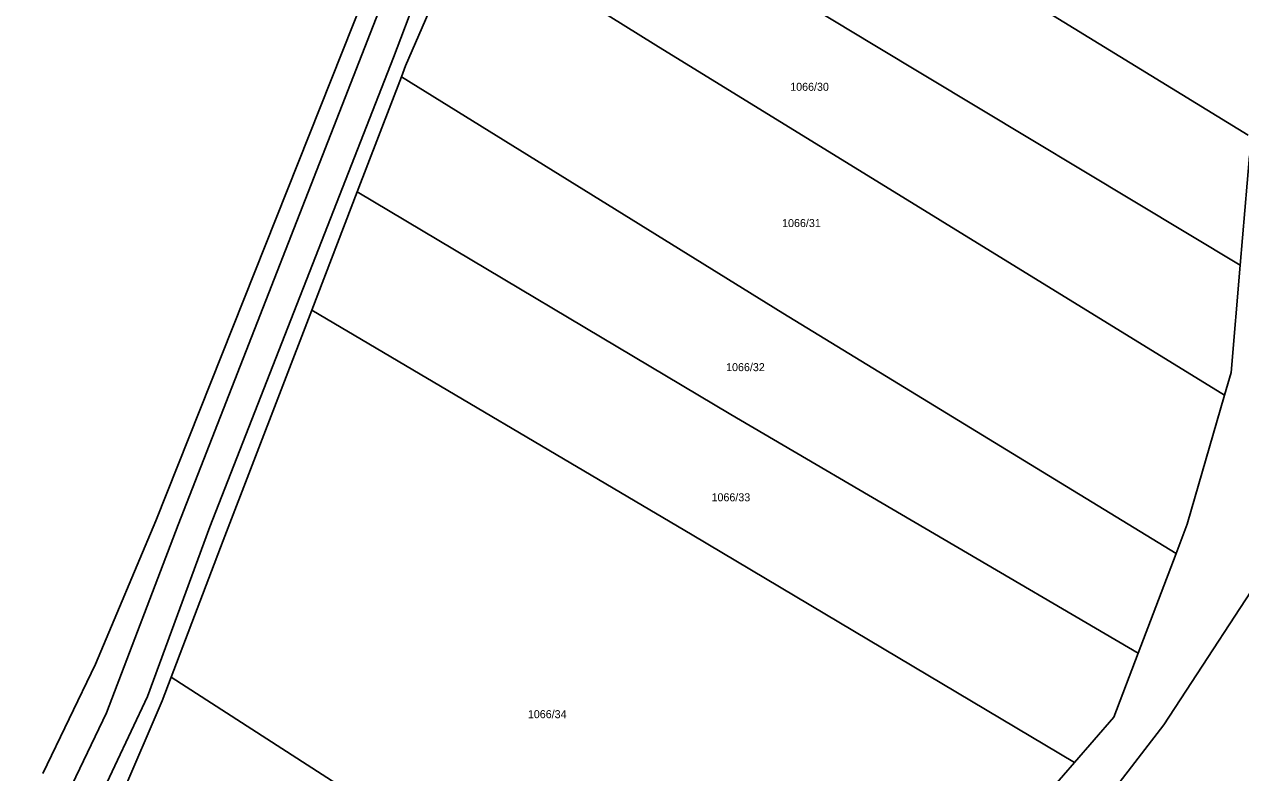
# Model space of a CAD drawing. Extents: x -794142 to -791199, y -1109267 to -1105626.
# Drawn here: x -791706.9 to -791448.6, y -1108817.8 to -1108658.8 of the extents above; entities that cross this region are included whole.
import ezdxf

# ---------------------------------------------------------------- set-up
doc = ezdxf.new("R2010")
doc.units = 0
for name, color, linetype in [('Vrstva 1', 7, 'Continuous'), ('Vrstva 14', 7, 'Continuous'), ('Vrstva 2', 7, 'Continuous')]:
    doc.layers.add(name, color=color, linetype=linetype)

msp = doc.modelspace()

# ---------------------------------------------------------------- linework, layer by layer
at = {"layer": 'Vrstva 1'}
for p, q in [((-791607.65, -1108614.07), (-791526.62, -1108663.13)), ((-791532.37, -1108630.01), (-791446.95, -1108682.34)), ((-791613.7, -1108637.7), (-791572.76, -1108663.24)), ((-791679, -1108764.32), (-791633.57, -1108649.97)), ((-791619.47, -1108652.6), (-791625.93, -1108667.65)), ((-791572.76, -1108663.24), (-791451.98, -1108737.62)), ((-791526.62, -1108663.13), (-791448.66, -1108709.97)), ((-791636.21, -1108694.4), (-791626.82, -1108669.96)), ((-791626.82, -1108669.96), (-791625.93, -1108667.65)), ((-791626.82, -1108669.96), (-791545.83, -1108720.15)), ((-791446.7, -1108686.74), (-791448.66, -1108709.97)), ((-791645.88, -1108719.56), (-791636.21, -1108694.4)), ((-791636.21, -1108694.4), (-791556.84, -1108741.69)), ((-791448.66, -1108709.97), (-791450.58, -1108732.78)), ((-791664.67, -1108768.47), (-791645.88, -1108719.56)), ((-791565.09, -1108767.29), (-791645.88, -1108719.56)), ((-791545.83, -1108720.15), (-791462.28, -1108771.24)), ((-791450.58, -1108732.78), (-791451.98, -1108737.62)), ((-791451.98, -1108737.62), (-791459.92, -1108765.01)), ((-791556.84, -1108741.69), (-791470.31, -1108792.39)), ((-791691.82, -1108794.77), (-791679, -1108764.32)), ((-791462.28, -1108771.24), (-791459.92, -1108765.01)), ((-791483.82, -1108815.6), (-791565.09, -1108767.29)), ((-791664.67, -1108768.47), (-791675.71, -1108797.47)), ((-791470.31, -1108792.39), (-791462.28, -1108771.24)), ((-791459, -1108798.61), (-791446.31, -1108779.26)), ((-791475.47, -1108806), (-791470.31, -1108792.39)), ((-791702.98, -1108817.98), (-791691.82, -1108794.77)), ((-791675.71, -1108797.47), (-791677.63, -1108802.52)), ((-791675.71, -1108797.47), (-791622.06, -1108832.09)), ((-791464.89, -1108807.59), (-791459, -1108798.61)), ((-791686.2, -1108822.51), (-791677.63, -1108802.52)), ((-791483.82, -1108815.6), (-791475.47, -1108806)), ((-791475.05, -1108820.89), (-791464.89, -1108807.59)), ((-791509.23, -1108844.82), (-791483.82, -1108815.6))]:
    msp.add_line(p, q, dxfattribs=at)
at = {"layer": 'Vrstva 2'}
for p, q in [((-791628.49, -1108665.85), (-791614.27, -1108628.33)), ((-791629.48, -1108650.48), (-791674.27, -1108765.12)), ((-791667.53, -1108765.55), (-791628.49, -1108665.85)), ((-791674.27, -1108765.12), (-791689.47, -1108805.06)), ((-791680.77, -1108801.61), (-791667.53, -1108765.55)), ((-791697.29, -1108836.73), (-791680.77, -1108801.61)), ((-791689.47, -1108805.06), (-791706.93, -1108841.47))]:
    msp.add_line(p, q, dxfattribs=at)

# ---------------------------------------------------------------- texts
at = {"layer": 'Vrstva 14'}
for s, p in [('1066/30', (-791544.241, -1108672.95)), ('1066/31', (-791545.966, -1108701.89)), ('1066/32', (-791557.862, -1108732.5)), ('1066/33', (-791560.952, -1108760.14)), ('1066/34', (-791599.968, -1108806.21))]:
    msp.add_text(s, height=1.7, dxfattribs=at).set_placement(p)

doc.saveas('drawing.dxf')
